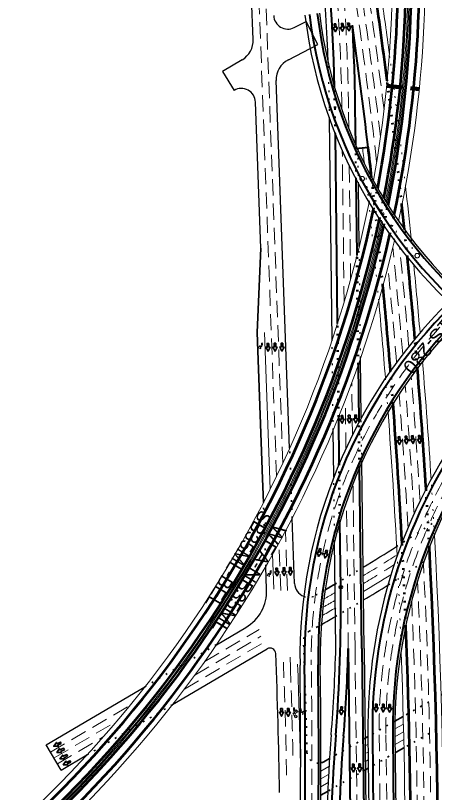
# Model space of a CAD drawing. Extents: x 2329387 to 2347382, y 6951580 to 6987999.
# Drawn here: x 2331270 to 2332013, y 6963710 to 6965088 of the extents above; entities that cross this region are included whole.
import ezdxf

# ---------------------------------------------------------------- set-up
doc = ezdxf.new("R2010")
doc.units = 0
doc.header["$LTSCALE"] = 9.6
doc.header["$PDMODE"] = 32
doc.header["$PDSIZE"] = 4.8
doc.linetypes.add('DOTTED', pattern=[1.5, 0.3, -1.2])
doc.linetypes.add('MEDIUM_DASHED', pattern=[4.5, 3, -1.5])
for name, color, linetype, lineweight in [('26', 7, 'Continuous', 53), ('27', 7, 'Continuous', 40), ('28', 7, 'Continuous', 25), ('29', 7, 'DOTTED', 35), ('30', 7, 'Continuous', 13), ('31', 7, 'Continuous', 53), ('41', 7, 'Continuous', 35), ('50', 7, 'MEDIUM_DASHED', 13)]:
    doc.layers.add(name, color=color, linetype=linetype, lineweight=lineweight)
doc.layers.add('40', color=7, linetype='Continuous')

msp = doc.modelspace()

# ---------------------------------------------------------------- linework, layer by layer
at = {"layer": '26', "lineweight": 13}
for centre, radius, start, end in [((2320619.05, 6963651.709), 11500.156, 4.81964, 8.12796), ((2321018.843, 6963569.511), 11010, 7.56884, 8.12795), ((2321018.843, 6963569.511), 10942, 6.59465, 6.74101), ((2321018.843, 6963569.511), 11010, 5.85732, 6.33967), ((2321018.843, 6963569.511), 11010, 4.9818, 5.60951), ((2321018.843, 6963569.511), 10942, 4.58755, 5.31124), ((2321018.843, 6963569.511), 11010, 3.6232, 4.71273), ((2321018.843, 6963569.511), 10942, 2.92492, 4.27289), ((2320619.05, 6963651.709), 11500.156, 348.37024, 3.35435), ((2321018.843, 6963569.511), 11010, 348.37024, 3.10741), ((2321018.843, 6963569.511), 10942, 352.02498, 2.03298)]:
    msp.add_arc(centre, radius, start, end, dxfattribs=at)
at = {"layer": '26'}
for centre, radius, start, end in [((2321018.843, 6963569.511), 11000, 7.32798, 8.12796), ((2321018.843, 6963569.511), 10952, 6.45748, 6.74101), ((2321018.843, 6963569.511), 11000, 5.94448, 6.17049), ((2321018.843, 6963569.511), 11000, 4.92971, 5.68689), ((2321018.843, 6963569.511), 10952, 4.65202, 5.44726), ((2321018.843, 6963569.511), 11000, 3.53759, 4.65538), ((2321018.843, 6963569.511), 10952, 3.04938, 4.34583), ((2320619.05, 6963651.709), 11510.156, 348.37024, 3.41668), ((2321018.843, 6963569.511), 11000, 348.37024, 2.99621), ((2321018.843, 6963569.511), 10952, 352.02498, 2.27299)]:
    msp.add_arc(centre, radius, start, end, dxfattribs=at)
at = {"layer": '26', "linetype": 'DOTTED', "lineweight": 13}
for radius, start, end in [(11010, 6.33967, 7.56885), (10942, 5.31124, 6.59465), (11010, 5.60951, 5.85732), (10942, 4.27288, 4.58755), (11010, 3.10741, 3.62319), (10942, 2.03298, 2.92492)]:
    msp.add_arc((2321018.843, 6963569.511), radius, start, end, dxfattribs=at)
at = {"layer": '26', "linetype": 'DOTTED'}
for radius, start, end in [(11000, 6.17049, 7.32798), (10952, 5.44726, 6.45748), (11000, 5.68689, 5.94448), (11000, 4.65538, 4.92971), (10952, 4.34583, 4.65202), (11000, 2.99621, 3.53759), (10952, 2.27299, 3.04938)]:
    msp.add_arc((2321018.843, 6963569.511), radius, start, end, dxfattribs=at)
at = {"layer": '27', "linetype": 'DOTTED', "lineweight": 25}
for p, q in [((2331826.653, 6964904.902), (2331826.427, 6964923.822)), ((2331878.034, 6964789.714), (2331877.32, 6964849.442)), ((2331881.731, 6964480.414), (2331879.366, 6964678.281)), ((2331833.253, 6964352.766), (2331831.345, 6964512.419)), ((2331883.947, 6964295.014), (2331883, 6964374.261)), ((2331835.622, 6964154.631), (2331834.252, 6964269.23))]:
    msp.add_line(p, q, dxfattribs=at)
at = {"layer": '27', "linetype": 'DOTTED'}
for p, q in [((2331836.98, 6964877.631), (2331836.426, 6964923.941)), ((2331873.283, 6964852.492), (2331873.21, 6964858.557)), ((2331873.941, 6964797.399), (2331873.283, 6964852.492))]:
    msp.add_line(p, q, dxfattribs=at)
at = {"layer": '27'}
for p, q in [((2331873.21, 6964858.557), (2331872.424, 6964924.371)), ((2331840.993, 6964541.898), (2331836.98, 6964877.631)), ((2331873.283, 6964852.492), (2331895.131, 6964855.075)), ((2331875.549, 6964662.926), (2331873.941, 6964797.399)), ((2331879.086, 6964367.012), (2331877.864, 6964469.25)), ((2331843.965, 6964293.271), (2331842.971, 6964376.46)), ((2331883.89, 6963965.211), (2331880.053, 6964286.126)), ((2331846.61, 6964072.063), (2331845.202, 6964189.819)), ((2331859.891, 6963964.924), (2331864.989, 6963538.523)), ((2331883.889, 6963965.211), (2331888.987, 6963538.81)), ((2331902.724, 6963811.829), (2331905.986, 6963539.014)), ((2331938.722, 6963812.26), (2331941.983, 6963539.444))]:
    msp.add_line(p, q, dxfattribs=at)
at = {"layer": '27', "lineweight": 25}
for p, q in [((2331831.345, 6964512.419), (2331826.653, 6964904.902)), ((2331877.32, 6964849.442), (2331877.278, 6964852.964)), ((2331879.366, 6964678.281), (2331878.034, 6964789.714)), ((2331883, 6964374.261), (2331881.731, 6964480.414)), ((2331834.252, 6964269.23), (2331833.253, 6964352.766)), ((2331887.889, 6963965.259), (2331883.947, 6964295.014)), ((2331837.865, 6963967.009), (2331835.622, 6964154.631)), ((2331887.889, 6963965.259), (2331892.986, 6963538.858)), ((2331894.725, 6963811.734), (2331897.986, 6963538.918)), ((2331942.721, 6963812.307), (2331945.983, 6963539.492))]:
    msp.add_line(p, q, dxfattribs=at)
at = {"layer": '27', "linetype": 'DOTTED', "lineweight": 53}
for p, q in [((2331877.864, 6964469.25), (2331875.549, 6964662.926)), ((2331842.971, 6964376.46), (2331840.993, 6964541.898)), ((2331880.053, 6964286.126), (2331879.086, 6964367.012)), ((2331845.202, 6964189.819), (2331843.965, 6964293.271))]:
    msp.add_line(p, q, dxfattribs=at)
at = {"layer": '27'}
for centre, radius, start, end in [((2339406.145, 6959556.474), 7976, 170.51466, 170.51466), ((2328562.616, 6964884.806), 3274.044, 1.33178, 8.12795), ((2332620.068, 6965189.757), 835, 186.84922, 291.74312), ((2332620.068, 6965189.757), 821, 186.84892, 289.1959), ((2321018.843, 6963569.511), 10952, 6.74101, 7.88061), ((2328562.616, 6964884.806), 3310.044, 0.68489, 3.22698), ((2332663.723, 6963948.074), 881.473, 134.70234, 180.79832), ((2332663.723, 6963948.074), 857.473, 134.61892, 180.79832), ((2332823.658, 6963822.838), 885, 134.33064, 180.6849), ((2332823.658, 6963822.838), 921, 143.69416, 180.6849), ((2328982.002, 6964039.758), 2864.789, 355.42223, 0.68489), ((2328982.002, 6964039.758), 2878.789, 355.42223, 358.51041), ((2319783.502, 6963768.598), 11999.998, 350.71583, 0.79832), ((2319783.502, 6963768.598), 12023.998, 353.14789, 0.79832), ((2334658.491, 6963585.255), 2829.866, 175.42223, 180.70842), ((2334658.491, 6963585.255), 2815.866, 175.42223, 180.70842)]:
    msp.add_arc(centre, radius, start, end, dxfattribs=at)
at = {"layer": '27', "lineweight": 25}
for centre, radius, start, end in [((2328562.616, 6964884.806), 3264.044, 2.09116, 8.12795), ((2332620.068, 6965189.757), 843, 186.84922, 237.06532), ((2332620.068, 6965189.757), 817, 186.84892, 237.40672), ((2332663.723, 6963948.074), 889.473, 134.71934, 180.79832), ((2332663.723, 6963948.074), 853.473, 134.60008, 180.79832), ((2332823.658, 6963822.838), 881, 134.2544, 180.6849), ((2332823.658, 6963822.838), 929, 143.69416, 180.6849), ((2328982.002, 6964039.758), 2856.789, 355.42223, 358.54079), ((2319783.502, 6963768.598), 11991.998, 350.71583, 0.79832), ((2319783.502, 6963768.598), 12027.998, 354.96558, 0.79832), ((2334658.491, 6963585.255), 2837.866, 175.42223, 180.70842)]:
    msp.add_arc(centre, radius, start, end, dxfattribs=at)
at = {"layer": '27', "linetype": 'DOTTED', "lineweight": 25}
msp.add_arc((2328562.616, 6964884.806), 3264.044, 0.68489, 2.09116, dxfattribs=at)
at = {"layer": '27', "linetype": 'DOTTED', "lineweight": 53}
msp.add_arc((2328562.616, 6964884.806), 3274.044, 0.68489, 1.33178, dxfattribs=at)
at = {"layer": '27'}
msp.add_point((2331846.587, 6964074.002), dxfattribs=at)
at = {"layer": '28'}
for p, q in [((2331691.234, 6965045.796), (2331677.775, 6965411.534)), ((2331764.015, 6965067.042), (2331785.234, 6965077.842)), ((2331806.162, 6965036.722), (2331785.234, 6965077.842)), ((2331753.771, 6965010.059), (2331806.162, 6965036.722)), ((2331671.713, 6965009.949), (2331636.656, 6964989.092)), ((2331636.656, 6964989.092), (2331657.488, 6964955.457)), ((2331755.956, 6964320.38), (2331731.941, 6964972.939)), ((2331704.856, 6964675.658), (2331695.314, 6964934.928)), ((2331764.79, 6964080.341), (2331760.509, 6964196.651)), ((2331715.14, 6964069.889), (2331713.633, 6964110.84)), ((2331626.032, 6963971.744), (2331678.258, 6964002.51)), ((2331548.301, 6963865.602), (2331716.226, 6963964.524)), ((2331324.417, 6963794.067), (2331499.279, 6963897.076)), ((2331350.811, 6963749.264), (2331324.417, 6963794.067)), ((2331350.811, 6963749.264), (2331396.54, 6963776.202))]:
    msp.add_line(p, q, dxfattribs=at)
at = {"layer": '28', "lineweight": 35}
for p, q in [((2331704.856, 6964675.658), (2331698.397, 6964525.717)), ((2331707.921, 6964266.048), (2331698.397, 6964525.717)), ((2331957.388, 6963844.479), (2331942.759, 6963836.137)), ((2331894.76, 6963808.763), (2331889.794, 6963805.931)), ((2331958.646, 6963788.789), (2331944.799, 6963780.892)), ((2331826.639, 6963769.914), (2331816.549, 6963764.16)), ((2331895.43, 6963752.737), (2331890.464, 6963749.905)), ((2331823.249, 6963711.573), (2331811.33, 6963704.776))]:
    msp.add_line(p, q, dxfattribs=at)
at = {"layer": '28', "linetype": 'DOTTED', "lineweight": 35}
for p, q in [((2332028.558, 6963828.659), (2331958.646, 6963788.789)), ((2331944.799, 6963780.892), (2331895.43, 6963752.737)), ((2331890.464, 6963749.905), (2331823.249, 6963711.573))]:
    msp.add_line(p, q, dxfattribs=at)
at = {"layer": '28'}
for centre, radius, start, end in [((2331752.675, 6965089.322), 25, 182.10758, 296.97353), ((2331651.261, 6965044.325), 40, 300.75049, 2.10758), ((2331771.914, 6964974.41), 40, 116.97361, 182.10758), ((2331670.331, 6964934.008), 25, 2.10758, 120.91372), ((2329901.512, 6967372.821), 3819.72, 301.30421, 302.3542), ((2331789.773, 6964081.26), 25, 182.10758, 249.57289), ((2329901.512, 6967372.821), 3869.72, 300.86703, 301.63059), ((2331640.191, 6964067.131), 75, 300.50171, 2.10758), ((2329901.512, 6967372.821), 3869.72, 299.58999, 300.01187), ((2331721.301, 6963955.908), 10, 2.26095, 120.5017), ((2321980.757, 6963571.336), 9758.134, 0.81201, 2.26095)]:
    msp.add_arc(centre, radius, start, end, dxfattribs=at)
at = {"layer": '28', "linetype": 'DOTTED'}
for centre, radius, start, end in [((2331789.773, 6964081.26), 25, 249.57289, 299.84149), ((2329901.512, 6967372.821), 3869.72, 299.51695, 299.58999)]:
    msp.add_arc(centre, radius, start, end, dxfattribs=at)
at = {"layer": '29'}
for p, q in [((2331760.509, 6964196.651), (2331755.956, 6964320.38)), ((2331713.633, 6964110.84), (2331709.461, 6964224.206)), ((2331930.95, 6964077.959), (2332014.462, 6964132.075)), ((2331790.704, 6963995.59), (2331808.049, 6964005.352)), ((2331499.279, 6963897.076), (2331626.032, 6963971.744)), ((2332027.679, 6963884.566), (2331957.388, 6963844.479)), ((2331396.54, 6963776.202), (2331548.301, 6963865.602)), ((2331942.759, 6963836.137), (2331894.76, 6963808.763)), ((2331889.794, 6963805.931), (2331826.639, 6963769.914))]:
    msp.add_line(p, q, dxfattribs=at)
at = {"layer": '29', "linetype": 'Continuous'}
msp.add_line((2331709.461, 6964224.206), (2331707.921, 6964266.048), dxfattribs=at)
at = {"layer": '29'}
for centre, radius, start, end in [((2329901.512, 6967372.821), 3819.72, 302.3542, 303.81653), ((2329901.512, 6967372.821), 3819.72, 300.43655, 301.30421), ((2329901.512, 6967372.821), 3819.72, 299.84149, 300.13027), ((2329901.512, 6967372.821), 3869.72, 300.01187, 300.86703), ((2331800.468, 6963978.136), 20, 119.22225, 182.37222), ((2321980.757, 6963571.336), 9808.134, 1.2255, 2.37223), ((2331806.642, 6963781.534), 20, 181.2255, 284.05148)]:
    msp.add_arc(centre, radius, start, end, dxfattribs=at)
at = {"layer": '29', "linetype": 'Continuous'}
for centre, radius, start, end in [((2329811.195, 6967527.482), 3998.82, 300.13713, 300.42969), ((2331806.642, 6963781.534), 20, 284.05148, 299.69572)]:
    msp.add_arc(centre, radius, start, end, dxfattribs=at)
at = {"layer": '30'}
for points in [[(2331707.661, 6964505.862), (2331707.465, 6964507.288), (2331705.919, 6964507.073), (2331706.093, 6964505.815)], [(2331703.512, 6964500.524), (2331703.215, 6964502.663), (2331700.558, 6964498.54)], [(2331700.558, 6964498.54), (2331704.905, 6964496.88), (2331704.058, 6964499.045)], [(2331718.975, 6964096.613), (2331718.678, 6964098.752), (2331716.021, 6964094.629)], [(2331716.021, 6964094.629), (2331720.368, 6964092.969), (2331719.521, 6964095.134)], [(2331723.124, 6964101.951), (2331722.928, 6964103.377), (2331721.382, 6964103.162), (2331721.556, 6964101.904)], [(2331764.401, 6963844.254), (2331761.727, 6963850.089), (2331763.554, 6963849.73), (2331762.889, 6963859.688), (2331764.445, 6963859.792), (2331764.541, 6963858.365)], [(2331774.943, 6963856.802), (2331774.997, 6963858.241), (2331776.556, 6963858.181), (2331776.508, 6963856.911)], [(2331764.127, 6963855.541), (2331764.512, 6963849.793), (2331766.275, 6963850.393), (2331764.401, 6963844.254)], [(2331767.889, 6963853.848), (2331767.745, 6963856.003), (2331771.337, 6963852.654), (2331767.153, 6963850.451), (2331767.761, 6963852.584)], [(2331782.738, 6963850.222), (2331778.576, 6963848.138), (2331779.205, 6963850.376)], [(2331779.6, 6963851.902), (2331779.683, 6963854.061), (2331782.738, 6963850.222)]]:
    msp.add_lwpolyline(points, dxfattribs=at)
for centre, radius, start, end in [((2331700.861, 6964505.092), 5.28, 300.11766, 7.8684), ((2331700.861, 6964505.092), 6.84, 297.85888, 6.46749), ((2331716.325, 6964101.181), 5.28, 300.11766, 7.8684), ((2331716.325, 6964101.181), 6.84, 297.85888, 6.46749), ((2331769.729, 6963858.711), 5.2, 183.82116, 249.27717), ((2331769.729, 6963858.711), 6.436, 209.51196, 252.19598), ((2331781.784, 6963856.711), 6.84, 179.22862, 247.83723), ((2331781.784, 6963856.711), 5.28, 177.82771, 245.57845)]:
    msp.add_arc(centre, radius, start, end, dxfattribs=at)
msp.add_point((2331766.994, 6963844.428), dxfattribs=at)
at = {"layer": '31', "lineweight": 13}
for radius, start, end in [(2054.483, 349.6074, 8.12795), (2082.483, 348.72065, 8.12795), (2084.483, 348.66216, 8.12795), (2112.483, 347.90133, 8.12795), (2054.483, 300.39505, 348.49858), (2082.483, 300.39505, 347.70072), (2084.483, 300.39505, 347.64774), (2112.483, 300.39505, 346.95514)]:
    msp.add_arc((2329883.662, 6965166.203), radius, start, end, dxfattribs=at)
at = {"layer": '31'}
for radius, start, end in [(2064.483, 349.27527, 8.12783), (2078.483, 348.83943, 8.12783), (2088.483, 348.54694, 8.12795), (2102.483, 348.16124, 8.12795), (2064.483, 300.39505, 348.20098), (2078.483, 300.39505, 347.80819), (2088.483, 300.39505, 347.54327), (2102.483, 300.39505, 347.19243)]:
    msp.add_arc((2329883.662, 6965166.203), radius, start, end, dxfattribs=at)
at = {"layer": '31', "linetype": 'DOTTED', "lineweight": 13}
for radius, start, end in [(2054.483, 348.49858, 349.6074), (2082.483, 347.70072, 348.72065), (2084.483, 347.64774, 348.66216), (2112.483, 346.95515, 347.90133)]:
    msp.add_arc((2329883.662, 6965166.203), radius, start, end, dxfattribs=at)
at = {"layer": '31', "linetype": 'DOTTED'}
for radius, start, end in [(2064.483, 348.20098, 349.27527), (2078.483, 347.80819, 348.83943), (2088.483, 347.54327, 348.54694), (2102.483, 347.19243, 348.16124)]:
    msp.add_arc((2329883.662, 6965166.203), radius, start, end, dxfattribs=at)
at = {"layer": '41'}
for points in [[(2331838.084, 6965073.715), (2331835.088, 6965073.543), (2331835.476, 6965066.748), (2331833.043, 6965066.609), (2331837.226, 6965059.636), (2331840.588, 6965067.04), (2331838.472, 6965066.919)], [(2331850.82, 6965074.532), (2331847.824, 6965074.361), (2331848.212, 6965067.566), (2331845.779, 6965067.426), (2331849.963, 6965060.454), (2331853.324, 6965067.858), (2331851.208, 6965067.737)], [(2331862.08, 6965075.138), (2331859.085, 6965074.967), (2331859.473, 6965068.171), (2331857.04, 6965068.032), (2331861.223, 6965061.059), (2331864.585, 6965068.464), (2331862.469, 6965068.343)], [(2331718.922, 6964506.569), (2331715.922, 6964506.485), (2331716.113, 6964499.681), (2331713.676, 6964499.613), (2331717.655, 6964492.521), (2331721.231, 6964499.824), (2331719.112, 6964499.765)], [(2331731.368, 6964506.776), (2331728.368, 6964506.692), (2331728.559, 6964499.888), (2331726.122, 6964499.82), (2331730.101, 6964492.728), (2331733.677, 6964500.031), (2331731.558, 6964499.972)], [(2331743.63, 6964506.867), (2331740.63, 6964506.783), (2331740.821, 6964499.979), (2331738.384, 6964499.911), (2331742.363, 6964492.819), (2331745.939, 6964500.123), (2331743.82, 6964500.063)], [(2331850.457, 6964378.818), (2331847.458, 6964378.72), (2331847.68, 6964371.917), (2331845.244, 6964371.837), (2331849.256, 6964364.764), (2331852.798, 6964372.084), (2331850.679, 6964372.015)], [(2331863.023, 6964379.271), (2331860.023, 6964379.173), (2331860.245, 6964372.37), (2331857.809, 6964372.291), (2331861.821, 6964365.217), (2331865.363, 6964372.537), (2331863.245, 6964372.468)], [(2331874.336, 6964379.535), (2331871.337, 6964379.437), (2331871.559, 6964372.634), (2331869.123, 6964372.554), (2331873.134, 6964365.481), (2331876.676, 6964372.801), (2331874.558, 6964372.731)], [(2331951.472, 6964341.13), (2331948.481, 6964340.888), (2331949.031, 6964334.103), (2331946.601, 6964333.907), (2331950.949, 6964327.035), (2331954.134, 6964334.517), (2331952.022, 6964334.346)], [(2331964.001, 6964342.188), (2331961.01, 6964341.946), (2331961.56, 6964335.161), (2331959.13, 6964334.964), (2331963.478, 6964328.093), (2331966.663, 6964335.574), (2331964.551, 6964335.403)], [(2331975.289, 6964342.996), (2331972.298, 6964342.754), (2331972.847, 6964335.969), (2331970.418, 6964335.773), (2331974.765, 6964328.901), (2331977.951, 6964336.383), (2331975.838, 6964336.211)], [(2331987.365, 6964343.243), (2331984.374, 6964343), (2331984.924, 6964336.216), (2331982.494, 6964336.019), (2331986.842, 6964329.148), (2331990.027, 6964336.629), (2331987.915, 6964336.458)], [(2331811.854, 6964141.75), (2331808.938, 6964142.46), (2331807.327, 6964135.847), (2331804.959, 6964136.424), (2331806.926, 6964128.534), (2331812.302, 6964134.635), (2331810.242, 6964135.137)], [(2331823.257, 6964138.898), (2331820.341, 6964139.608), (2331818.73, 6964132.995), (2331816.362, 6964133.572), (2331818.329, 6964125.682), (2331823.705, 6964131.783), (2331821.646, 6964132.285)], [(2331734.632, 6964107.883), (2331731.635, 6964107.728), (2331731.987, 6964100.931), (2331729.553, 6964100.805), (2331733.698, 6964093.809), (2331737.1, 6964101.195), (2331734.984, 6964101.086)], [(2331747.187, 6964108.576), (2331744.19, 6964108.421), (2331744.541, 6964101.623), (2331742.107, 6964101.497), (2331746.253, 6964094.502), (2331749.655, 6964101.888), (2331747.538, 6964101.778)], [(2331758.493, 6964109.055), (2331755.496, 6964108.9), (2331755.848, 6964102.102), (2331753.414, 6964101.976), (2331757.559, 6964094.981), (2331760.961, 6964102.367), (2331758.844, 6964102.257)], [(2331742.999, 6963858.849), (2331739.999, 6963858.786), (2331740.143, 6963851.981), (2331737.706, 6963851.929), (2331741.636, 6963844.81), (2331745.262, 6963852.089), (2331743.143, 6963852.044)], [(2331754.96, 6963858.738), (2331751.96, 6963858.675), (2331752.103, 6963851.87), (2331749.667, 6963851.818), (2331753.597, 6963844.699), (2331757.223, 6963851.978), (2331755.103, 6963851.933)], [(2331849.713, 6963861.374), (2331846.716, 6963861.526), (2331846.37, 6963854.728), (2331843.936, 6963854.852), (2331847.345, 6963847.469), (2331851.484, 6963854.468), (2331849.367, 6963854.576)], [(2331911.095, 6963866.5), (2331908.095, 6963866.563), (2331907.951, 6963859.758), (2331905.514, 6963859.809), (2331909.14, 6963852.531), (2331913.07, 6963859.65), (2331910.951, 6963859.694)], [(2331923.667, 6963866.277), (2331920.667, 6963866.341), (2331920.523, 6963859.535), (2331918.086, 6963859.587), (2331921.712, 6963852.309), (2331925.642, 6963859.427), (2331923.523, 6963859.472)], [(2331934.978, 6963865.933), (2331931.978, 6963865.996), (2331931.834, 6963859.191), (2331929.397, 6963859.242), (2331933.023, 6963851.964), (2331936.953, 6963859.083), (2331934.834, 6963859.128)], [(2331350.904, 6963796.373), (2331349.594, 6963799.073), (2331343.47, 6963796.103), (2331342.406, 6963798.296), (2331337.576, 6963791.755), (2331345.704, 6963791.496), (2331344.779, 6963793.403)], [(2331356.392, 6963785.455), (2331355.082, 6963788.155), (2331348.958, 6963785.185), (2331347.894, 6963787.379), (2331343.064, 6963780.837), (2331351.192, 6963780.578), (2331350.267, 6963782.485)], [(2331361.996, 6963774.074), (2331360.686, 6963776.774), (2331354.562, 6963773.804), (2331353.498, 6963775.998), (2331348.668, 6963769.456), (2331356.796, 6963769.197), (2331355.871, 6963771.104)], [(2331367.712, 6963763.332), (2331366.403, 6963766.032), (2331360.278, 6963763.063), (2331359.215, 6963765.256), (2331354.385, 6963758.714), (2331362.512, 6963758.455), (2331361.587, 6963760.363)], [(2331870.205, 6963759.98), (2331867.206, 6963759.882), (2331867.428, 6963753.079), (2331864.992, 6963753), (2331869.004, 6963745.927), (2331872.546, 6963753.246), (2331870.427, 6963753.177)], [(2331881.519, 6963760.244), (2331878.52, 6963760.146), (2331878.742, 6963753.343), (2331876.306, 6963753.263), (2331880.317, 6963746.19), (2331883.859, 6963753.51), (2331881.741, 6963753.441)]]:
    msp.add_lwpolyline(points, close=True, dxfattribs=at)
at = {"layer": '50'}
for p, q in [((2331732.763, 6964270.811), (2331690.766, 6965412.012)), ((2331743.91, 6964294.206), (2331702.758, 6965412.453)), ((2331848.46, 6964921.224), (2331848.425, 6964924.084)), ((2331860.858, 6964887.946), (2331860.424, 6964924.228)), ((2331852.546, 6964579.35), (2331849.332, 6964848.267)), ((2331864.067, 6964619.489), (2331861.65, 6964821.72)), ((2331867.357, 6964344.262), (2331866.25, 6964436.868)), ((2331855.649, 6964319.8), (2331854.619, 6964405.995)), ((2331871.89, 6963965.067), (2331868.392, 6964257.697)), ((2331859.891, 6963964.924), (2331856.77, 6964226.003)), ((2331752.227, 6964068.204), (2331748.353, 6964173.473)), ((2331740.221, 6964068.162), (2331737.112, 6964152.64)), ((2331605.387, 6963942.173), (2331701.924, 6963999.042)), ((2331587.905, 6963917.948), (2331705.076, 6963986.971)), ((2331569.47, 6963893.161), (2331711.235, 6963976.672)), ((2331871.89, 6963965.067), (2331876.988, 6963538.667)), ((2331745.28, 6963930.679), (2331744.896, 6963941.131)), ((2331757.272, 6963931.114), (2331756.587, 6963949.729)), ((2331332.031, 6963781.143), (2331472.793, 6963864.064)), ((2331338.122, 6963770.804), (2331449.959, 6963836.685)), ((2331958.039, 6963817.222), (2331942.767, 6963808.513)), ((2331344.212, 6963760.465), (2331425.414, 6963808.299)), ((2331914.723, 6963811.973), (2331917.985, 6963539.157)), ((2331926.723, 6963812.116), (2331929.984, 6963539.301)), ((2331958.339, 6963803.579), (2331942.931, 6963794.792)), ((2331895.088, 6963781.322), (2331890.122, 6963778.49)), ((2331895.252, 6963767.601), (2331890.286, 6963764.769)), ((2331824.918, 6963741.305), (2331811.449, 6963733.623)), ((2331824.17, 6963727.064), (2331811.401, 6963719.781))]:
    msp.add_line(p, q, dxfattribs=at)
at = {"layer": '50', "lineweight": 106}
msp.add_line((2331927.446, 6964963.591), (2331986.361, 6964957.904), dxfattribs=at)
at = {"layer": '50', "linetype": 'Continuous'}
for p, q in [((2331721.589, 6964248.092), (2331711.389, 6964526.193)), ((2331728.107, 6964070.366), (2331725.836, 6964132.288)), ((2331957.722, 6963830.855), (2331942.659, 6963822.265)), ((2331894.924, 6963795.043), (2331889.958, 6963792.21)), ((2331825.741, 6963755.588), (2331811.481, 6963747.456))]:
    msp.add_line(p, q, dxfattribs=at)
at = {"layer": '50'}
for centre in [(2331884.535, 6964798.823), (2331982.211, 6964662.338)]:
    msp.add_circle(centre, 4, dxfattribs=at)
for centre, radius, start, end in [((2328562.616, 6964884.806), 3286.044, 0.68489, 8.12795), ((2328562.616, 6964884.806), 3298.044, 0.68489, 8.12795), ((2321018.843, 6963569.511), 10964, 6.59599, 8.12796), ((2321018.843, 6963569.511), 10976, 6.82149, 8.12796), ((2321018.843, 6963569.511), 10988, 7.06405, 8.12796), ((2328562.616, 6964884.806), 3286.044, 0.68489, 0.7997), ((2321018.843, 6963569.511), 10976, 4.79698, 5.79269), ((2321018.843, 6963569.511), 10988, 4.86477, 5.78513), ((2321018.843, 6963569.511), 10964, 4.72614, 5.61641), ((2332663.723, 6963948.074), 869.473, 134.66686, 180.79832), ((2332823.658, 6963822.838), 909, 134.74537, 180.6849), ((2332823.658, 6963822.838), 897, 134.54695, 180.6849), ((2321018.843, 6963569.511), 10988, 3.42869, 4.58358), ((2321018.843, 6963569.511), 10976, 3.31204, 4.50827), ((2321018.843, 6963569.511), 10964, 3.18625, 4.42914), ((2320619.05, 6963651.709), 11546.156, 348.37024, 3.62206), ((2320619.05, 6963651.709), 11534.156, 348.37024, 3.55667), ((2320619.05, 6963651.709), 11522.156, 348.37024, 3.48829), ((2329901.512, 6967372.821), 3832.72, 301.18926, 302.24429), ((2321018.843, 6963569.511), 10988, 348.34293, 2.85027), ((2329901.512, 6967372.821), 3844.72, 301.08395, 302.02756), ((2321018.843, 6963569.511), 10976, 348.37024, 2.68674), ((2329901.512, 6967372.821), 3832.72, 300.00635, 300.32999), ((2329901.512, 6967372.821), 3844.72, 299.87099, 300.23262), ((2321018.843, 6963569.511), 10964, 348.37024, 2.49877), ((2319783.502, 6963768.598), 12011.998, 350.71583, 0.79832), ((2321980.757, 6963571.336), 9771.134, 0.9903, 2.10758), ((2321980.757, 6963571.336), 9783.134, 1.1952, 2.10754)]:
    msp.add_arc(centre, radius, start, end, dxfattribs=at)
at = {"layer": '50', "linetype": 'Continuous'}
for centre, radius, start, end in [((2329901.512, 6967372.821), 3856.72, 300.97942, 301.82871), ((2329901.512, 6967372.821), 3856.72, 299.74146, 300.13473), ((2321980.757, 6963571.336), 9796.134, 1.16352, 2.14086)]:
    msp.add_arc(centre, radius, start, end, dxfattribs=at)

# ---------------------------------------------------------------- texts
at = {"layer": '40'}
for s, rotation, width, p in [('121S-280', 229.862, 1.1, (2332053.725, 6964582.326)), ('WEA-NB35ML', 238.725, 1.05, (2331731.022, 6964187.707))]:
    msp.add_text(s, height=24, rotation=rotation, dxfattribs=dict(at, width=width)).set_placement(p)
msp.add_text('SB35ML-BEL', height=24, rotation=239.267, dxfattribs=at).set_placement((2331704.884, 6964212.728))

doc.saveas('drawing.dxf')
